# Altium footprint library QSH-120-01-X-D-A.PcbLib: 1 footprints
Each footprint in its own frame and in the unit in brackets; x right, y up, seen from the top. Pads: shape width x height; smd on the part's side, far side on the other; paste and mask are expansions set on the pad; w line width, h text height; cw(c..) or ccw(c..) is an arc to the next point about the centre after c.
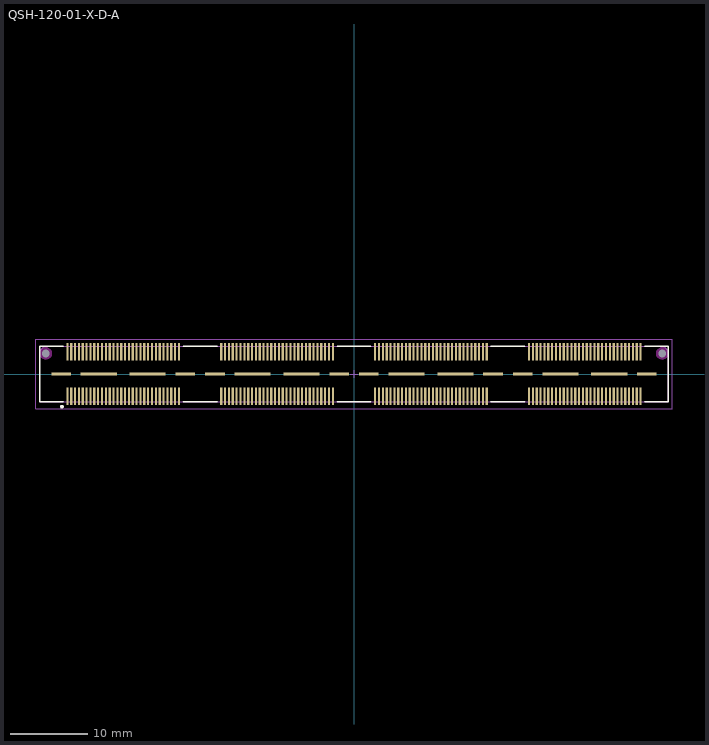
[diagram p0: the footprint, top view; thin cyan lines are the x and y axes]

## QSH-120-01-X-D-A [mm] "0.50mm pitch, 240 pin, high speed socket strip"
height 3.25
pads (258):
  rect 0.28x2.27 smd mask+0: 1(-37.25,-2.87) 2(-37.25,2.87) 3(-36.75,-2.87) 4(-36.75,2.87) 5(-36.25,-2.87) 6(-36.25,2.87) 7(-35.75,-2.87) 8(-35.75,2.87) 9(-35.25,-2.87) 10(-35.25,2.87) 11(-34.75,-2.87) 12(-34.75,2.87) 13(-34.25,-2.87) 14(-34.25,2.87) 15(-33.75,-2.87) 16(-33.75,2.87) 17(-33.25,-2.87) 18(-33.25,2.87) 19(-32.75,-2.87) 20(-32.75,2.87) 21(-32.25,-2.87) 22(-32.25,2.87) 23(-31.75,-2.87) 24(-31.75,2.87) 25(-31.25,-2.87) 26(-31.25,2.87) 27(-30.75,-2.87) 28(-30.75,2.87) 29(-30.25,-2.87) 30(-30.25,2.87) 31(-29.75,-2.87) 32(-29.75,2.87) 33(-29.25,-2.87) 34(-29.25,2.87) 35(-28.75,-2.87) 36(-28.75,2.87) 37(-28.25,-2.87) 38(-28.25,2.87) 39(-27.75,-2.87) 40(-27.75,2.87) 41(-27.25,-2.87) 42(-27.25,2.87) 43(-26.75,-2.87) 44(-26.75,2.87) 45(-26.25,-2.87) 46(-26.25,2.87) 47(-25.75,-2.87) 48(-25.75,2.87) 49(-25.25,-2.87) 50(-25.25,2.87) 51(-24.75,-2.87) 52(-24.75,2.87) 53(-24.25,-2.87) 54(-24.25,2.87) 55(-23.75,-2.87) 56(-23.75,2.87) 57(-23.25,-2.87) 58(-23.25,2.87) 59(-22.75,-2.87) 60(-22.75,2.87) 61(-17.25,-2.87) 62(-17.25,2.87) 63(-16.75,-2.87) 64(-16.75,2.87) 65(-16.25,-2.87) 66(-16.25,2.87) 67(-15.75,-2.87) 68(-15.75,2.87) 69(-15.25,-2.87) 70(-15.25,2.87) 71(-14.75,-2.87) 72(-14.75,2.87) 73(-14.25,-2.87) 74(-14.25,2.87) 75(-13.75,-2.87) 76(-13.75,2.87) 77(-13.25,-2.87) 78(-13.25,2.87) 79(-12.75,-2.87) 80(-12.75,2.87) 81(-12.25,-2.87) 82(-12.25,2.87) 83(-11.75,-2.87) 84(-11.75,2.87) 85(-11.25,-2.87) 86(-11.25,2.87) 87(-10.75,-2.87) 88(-10.75,2.87) 89(-10.25,-2.87) 90(-10.25,2.87) 91(-9.75,-2.87) 92(-9.75,2.87) 93(-9.25,-2.87) 94(-9.25,2.87) 95(-8.75,-2.87) 96(-8.75,2.87) 97(-8.25,-2.87) 98(-8.25,2.87) 99(-7.75,-2.87) 100(-7.75,2.87) 101(-7.25,-2.87) 102(-7.25,2.87) 103(-6.75,-2.87) 104(-6.75,2.87) 105(-6.25,-2.87) 106(-6.25,2.87) 107(-5.75,-2.87) 108(-5.75,2.87) 109(-5.25,-2.87) 110(-5.25,2.87) 111(-4.75,-2.87) 112(-4.75,2.87) 113(-4.25,-2.87) 114(-4.25,2.87) 115(-3.75,-2.87) 116(-3.75,2.87) 117(-3.25,-2.87) 118(-3.25,2.87) 119(-2.75,-2.87) 120(-2.75,2.87) 121(2.75,-2.87) 122(2.75,2.87) 123(3.25,-2.87) 124(3.25,2.87) 125(3.75,-2.87) 126(3.75,2.87) 127(4.25,-2.87) 128(4.25,2.87) 129(4.75,-2.87) 130(4.75,2.87) 131(5.25,-2.87) 132(5.25,2.87) 133(5.75,-2.87) 134(5.75,2.87) 135(6.25,-2.87) 136(6.25,2.87) 137(6.75,-2.87) 138(6.75,2.87) 139(7.25,-2.87) 140(7.25,2.87) 141(7.75,-2.87) 142(7.75,2.87) 143(8.25,-2.87) 144(8.25,2.87) 145(8.75,-2.87) 146(8.75,2.87) 147(9.25,-2.87) 148(9.25,2.87) 149(9.75,-2.87) 150(9.75,2.87) 151(10.25,-2.87) 152(10.25,2.87) 153(10.75,-2.87) 154(10.75,2.87) 155(11.25,-2.87) 156(11.25,2.87) 157(11.75,-2.87) 158(11.75,2.87) 159(12.25,-2.87) 160(12.25,2.87) 161(12.75,-2.87) 162(12.75,2.87) 163(13.25,-2.87) 164(13.25,2.87) 165(13.75,-2.87) 166(13.75,2.87) 167(14.25,-2.87) 168(14.25,2.87) 169(14.75,-2.87) 170(14.75,2.87) 171(15.25,-2.87) 172(15.25,2.87) 173(15.75,-2.87) 174(15.75,2.87) 175(16.25,-2.87) 176(16.25,2.87) 177(16.75,-2.87) 178(16.75,2.87) 179(17.25,-2.87) 180(17.25,2.87) 181(22.75,-2.87) 182(22.75,2.87) 183(23.25,-2.87) 184(23.25,2.87) 185(23.75,-2.87) 186(23.75,2.87) 187(24.25,-2.87) 188(24.25,2.87) 189(24.75,-2.87) 190(24.75,2.87) 191(25.25,-2.87) 192(25.25,2.87) 193(25.75,-2.87) 194(25.75,2.87) 195(26.25,-2.87) 196(26.25,2.87) 197(26.75,-2.87) 198(26.75,2.87) 199(27.25,-2.87) 200(27.25,2.87) 201(27.75,-2.87) 202(27.75,2.87) 203(28.25,-2.87) 204(28.25,2.87) 205(28.75,-2.87) 206(28.75,2.87) 207(29.25,-2.87) 208(29.25,2.87) 209(29.75,-2.87) 210(29.75,2.87) 211(30.25,-2.87) 212(30.25,2.87) 213(30.75,-2.87) 214(30.75,2.87) 215(31.25,-2.87) 216(31.25,2.87) 217(31.75,-2.87) 218(31.75,2.87) 219(32.25,-2.87) 220(32.25,2.87) 221(32.75,-2.87) 222(32.75,2.87) 223(33.25,-2.87) 224(33.25,2.87) 225(33.75,-2.87) 226(33.75,2.87) 227(34.25,-2.87) 228(34.25,2.87) 229(34.75,-2.87) 230(34.75,2.87) 231(35.25,-2.87) 232(35.25,2.87) 233(35.75,-2.87) 234(35.75,2.87) 235(36.25,-2.87) 236(36.25,2.87) 237(36.75,-2.87) 238(36.75,2.87) 239(37.25,-2.87) 240(37.25,2.87)
  rect 2.54x0.43 smd mask+0: 241(-38.065,0) 244(-21.935,0) 245(-18.065,0) 248(-1.935,0) 249(1.935,0) 252(18.065,0) 253(21.935,0) 256(38.065,0)
  rect 4.7x0.43 smd mask+0: 242(-33.175,0) 243(-26.825,0) 246(-13.175,0) 247(-6.825,0) 250(6.825,0) 251(13.175,0) 254(26.825,0) 255(33.175,0)
  round 0.5 hole 1 unplated mask+0: 257(-40.065,2.67) 258(40.065,2.67)
Top Overlay:
  circle w0.25: c-37.95,-4.25 r0.125
  lines w0.2: -37.8,-3.6 -40.85,-3.6 -40.85,3.6 -37.8,3.6 ; -22.2,-3.6 -17.8,-3.6 ; -22.2,3.6 -17.8,3.6 ; -2.2,-3.6 2.2,-3.6 ; -2.2,3.6 2.2,3.6 ; 17.8,-3.6 22.2,-3.6 ; 17.8,3.6 22.2,3.6 ; 37.8,-3.6 40.85,-3.6 40.85,3.6 37.8,3.6
Keep-Out Layer:
  pour cut-out: 40.872,2.67 40.844,2.879 40.764,3.073 40.636,3.241 40.468,3.369 40.274,3.449 40.065,3.477 39.856,3.449 39.662,3.369 39.494,3.241 39.366,3.073 39.286,2.879 39.258,2.67 39.286,2.461 39.366,2.267 39.494,2.099 39.662,1.971 39.856,1.891 40.065,1.863 40.274,1.891 40.468,1.971 40.636,2.099 40.764,2.267 40.844,2.461
  pour cut-out: -39.258,2.67 -39.286,2.879 -39.366,3.073 -39.494,3.241 -39.662,3.369 -39.856,3.449 -40.065,3.477 -40.274,3.449 -40.468,3.369 -40.636,3.241 -40.764,3.073 -40.844,2.879 -40.872,2.67 -40.844,2.461 -40.764,2.267 -40.636,2.099 -40.468,1.971 -40.274,1.891 -40.065,1.863 -39.856,1.891 -39.662,1.971 -39.494,2.099 -39.366,2.267 -39.286,2.461
Mechanical 12:
  lines w0.001: -40.85,-3.6 -40.85,3 -40.25,3.6 40.25,3.6 40.85,3 40.85,-3.6 -40.85,-3.6
Mechanical 13:
  lines w0.1: -40.85,-3.6 -40.85,3 -40.25,3.6 40.25,3.6 40.85,3 40.85,-3.6 -40.85,-3.6
  text ".Designator" at 0.254,0.127 h1.52
Mechanical 15:
  lines w0.05: -0.5,0 0.5,0 ; 0,-0.5 0,0.5 ; -41.35,-4.5 -41.35,4.5 41.35,4.5 41.35,-4.5 -41.35,-4.5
